(* Logix 5000 project; controller Test vendor 1 type 14 code 92 rev 33.11; software revision 33.00 *)

TASK MainTask (continuous, watchdog 500 ms) : MainProgram

MODULES
   Local : vendor 1 type 14 code 92 (ICP 0, rev 33.11)
      IN : vendor 1 type 7 code 1 (ICP 3, rev 3.2, Input RPI 20 ms)
      O : vendor 1 type 7 code 15 (ICP 2, rev 3.2, Output RPI 20 ms)
      Ethernet : 1756-ENBT (ICP 1, Ethernet 192.168.0.98, rev 6.4)
         IOLM1 : DXM (Ethernet 192.168.0.1, rev 2.22, StandardDataDriven RPI 20 ms)
END_MODULES

TYPE Banner_CL50Pro_PDO_v4 :   // UDT that records the converted prcoess data.
STRUCT
   Color1 : SINT;   // 0 = Green, 1 = Red, 2 = Orange, 3 = Amber, 4 = Yellow, 5 = Lime Green, 6 = Spring Green, 7 = Cyan, 8 = SKy Blue, 9 = Blue, 10 = Violet, 11 = Magenta, 12 = Rose, 13 = White, 14 Custom 1, 15 = Custom 2.
   Color2 : SINT;   // 0 = Green, 1 = Red, 2 = Orange, 3 = Amber, 4 = Yellow, 5 = Lime Green, 6 = Spring Green, 7 = Cyan, 8 = SKy Blue, 9 = Blue, 10 = Violet, 11 = Magenta, 12 = Rose, 13 = White, 14 Custom 1, 15 = Custom 2.
   Animation : SINT;   // 0 = Off, 1 = Steady, 2 = Flash, 3 = Two Color Flash, 5 = Intensity Sweep
   Pulse_Pattern : SINT;   // 0 = Normal, 1 = Strobe, 2 = Three Pulse, 3 = SOS, 4 = Random
   Speed : SINT;   // 0 = Medium, 1 = Fast, 2 = Slow
   Color1_Intensity : SINT;   // 0 = High, 1 = Low, 2 = Medium, 3 = Off, 4 = Custom
   Color2_Intensity : SINT;   // 0 = High, 1 = Low, 2 = Medium, 3 = Off, 4 = Custom
   Audible_State : SINT;   // 0 = Off, 1 = On, 2 = Pulsed, 3 = SOS Pulse
   PDO_DT : SINT[4];
END_STRUCT
END_TYPE

TYPE Banner_CL50Pro_RD_v4 :   // UDT with all of the Read only parameters for CL50 Pro.
STRUCT
   Master_Cycle_Time : INT;
   Min_Cycle_Time : INT;
   M_Sequence_Capability : INT;
   IO_Link_Version_ID : INT;
   Process_Data_Input_Length : INT;
   Process_Data_Output_Length : INT;
   Combined_Vendor_ID : DINT;   // IO-Link Vendor ID
   Vendor_ID1 : INT;
   Vendor_ID2 : INT;
   Combined_Device_ID : DINT;   // IO-Link Device ID
   Device_ID1 : INT;
   Device_ID2 : INT;
   Device_ID3 : INT;
   Serial_Number : STRING;
END_STRUCT
END_TYPE

TYPE Banner_CL50Pro_v4 :   // UDT with all of the parameters for CL50 Pro.
STRUCT
   Initial_Global_Read : BOOL;   // Determines if all of the IO-Link data has been read into the PLC yet
   Command : INT;   // Value placed in here will activate a read or write to a specifc IO-Link Index
   Read_Data : Banner_CL50Pro_RD_v4;   // All read data
   Write_Data : Banner_CL50Pro_WD_v4;   // All data that can be written to.
   Archive : Banner_CL50Pro_WD_v4;   // Archive of the write data.
   Reset : BOOL;
END_STRUCT
END_TYPE

TYPE Banner_CL50Pro_WD_v4 :   // UDT that stores the Write Data for a CL50 Pro.
STRUCT
   System_Command : INT;   // See IODD file for list of commands that can be activated via the System Command interface
   Parameter_Access_Lock : SINT;   // Write access to all read/write parameters is block when this bit is ON.
   Data_Storage_Lock : SINT;   // Data storage mechanism is inhibited when bit is ON.
   Local_Parameterization_Lock : SINT;   // Parameteriation via local control elementes is inhibited.
   Local_User_Interface_Lock : SINT;   // Operation of the hmi on the device is disabled.
   Operating_Mode : SINT;   // 2 = Run Mode
   Custom_Intensity : SINT;   // 0 to 100 %
   Custom_Flash_Rate : INT;   // Range 5 to 255 (.5 to 25.5 converted rate).
   Number_of_Segments : INT;   // Number of Segments for Scroll and Bounce in the primary color.
   Restrict_to_Gamut : SINT;   // 0 = Off, 1 = On. Turn on to show more consistent colors from segment to segment.
   Disable_Parameter_Data : SINT;   // 0 = Disable, 1 = Enabled.
   Reserved : SINT;
   CC1_Red : INT;   // 0-255. Custom 1 Red.
   CC1_Green : INT;   // 0-255. Custom 1 Green.
   CC1_Blue : INT;   // 0-255. Custom 1 Blue.
   CC2_Red : INT;   // 0-255. Custom 2 Red.
   CC2_Green : INT;   // 0-255. Custom 2 Green.
   CC2_Blue : INT;   // 0-255. Custom 2 Blue.
END_STRUCT
END_TYPE

TYPE Banner_IOL_Port_v4 :   // UDT that has all of the data items necessary to communicate with a specific Port on a IO-Link Master
STRUCT
   Port_Controlled : INT;   // Each bit represents a port on an IO-Link Master. Set to 1 to tell AOI to control that port.
   Port_Activate : INT;   // Each bit represents a port on an IO-Link Master. When ON that port will process any commands in queue.
   Port_Read : INT;   // Each bit represents a port on an IO-Link Master. Used to determine when device AOI has requested a Read command.
   Port_Write : INT;   // Each bit represents a port on an IO-Link Master. Used to determine when device AOI has requested a Write command.
   Port_RW_Complete : INT;   // Each bit represents a port on an IO-Link Master. Tells device AOI that Read or Write request has been completed.
   Port_Device_Read : INT;
   Data_Transfer : SINT[190];   // Array to transfer data from IO-Master to device AOIs.
END_STRUCT
END_TYPE

TYPE Banner_IOLM_EL_v4 :   // Error Log for Messages to IOLM.
STRUCT
   RW : SINT;   // 0 = Read, 1 = Write.
   Port : SINT;   // Port number that generated error.
   Index : INT;   // IO-Link Index for generated error.
END_STRUCT
END_TYPE

TYPE Banner_IOLM_v4 :   // UDT to control IO-Link Masters.
STRUCT
   Message_Source_Data : SINT[190];
   Message_Destination_Data : SINT[190];
   Error_Log : Banner_IOLM_EL_v4[10];
   Error_Write_Retry : BOOL;
   Num_Error_MSGS : DINT;
   IO_Link_Master_Busy : BOOL;   // 0 = While waiting for a command, 1 = Processing command
   AOI_Reset : BOOL;
   Port_Data : Banner_IOL_Port_v4;   // All of the necessary data to work with the various ports of the IO-Link Master.
   Halt_Operation : BOOL;   // When parameter is 1 the AOI is halted as next available time frame.
   AOI_Halted : BOOL;   // AOI is in standby mode until Halt Operation tag is set back to 0.
END_STRUCT
END_TYPE

ADD_ON_INSTRUCTION Banner_CL50Pro_Param_v4   (* revision 4.0, vendor Banner Engineering *)
// AOI to read and write parameter data to an IO-Link CL50 Pro.
VAR_IN_OUT
   CL50Pro : Banner_CL50Pro_v4; {required}
   Port_Data : Banner_IOL_Port_v4; {required}
END_VAR
VAR_INPUT
   Port : DINT; {required}
END_VAR
VAR
   Local_Control : DINT; {access None}
   Global_Read_Command_Value : INT; {access None}
   Global_Write_Command_Value : INT; {access None}
   Command_Being_Processed : BOOL; {access None}
   Update_Archive : BOOL; {access None}
   Index_Write_Control : DINT; {access None}
   Index_Write_Inprocess : INT; {access None}
   Temp_Excess_Gain : DINT[2]; {access None}
   Inprocess_Index : DINT; {access None}
   SP_Index : DINT; {access None}   // State Parameters Index
   SP_Write_Index : DINT; {access None}
   SP_R_Index : DINT; {access None}
   SP_W_Index : DINT; {access None}
END_VAR

ROUTINE Logic   (* ladder *)
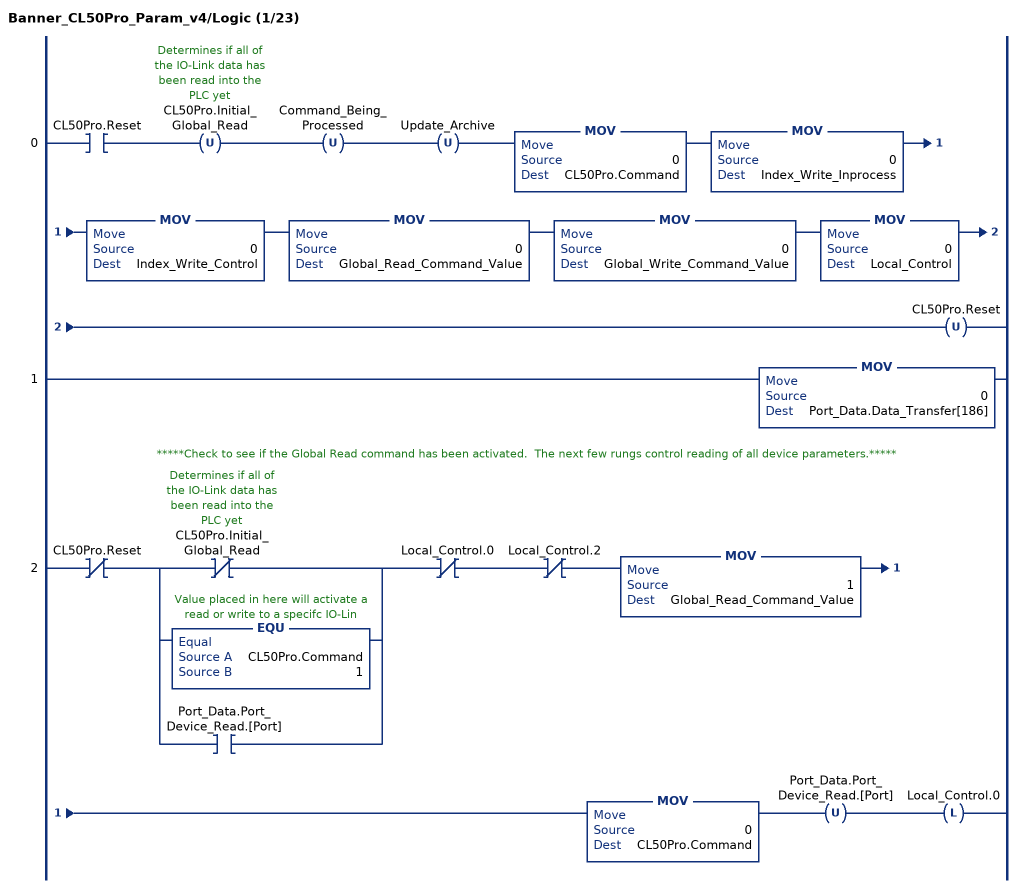
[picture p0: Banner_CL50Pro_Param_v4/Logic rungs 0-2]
   0: XIC(CL50Pro.Reset)OTU(CL50Pro.Initial_Global_Read)OTU(Command_Being_Processed)OTU(Update_Archive)MOV(0,CL50Pro.Command)MOV(0,Index_Write_Inprocess)MOV(0,Index_Write_Control)MOV(0,Global_Read_Command_Value)MOV(0,Global_Write_Command_Value)MOV(0,Local_Control)OTU(CL50Pro.Reset);
   1: MOV(0,Port_Data.Data_Transfer[186]);
   // *****Check to see if the Global Read command has been activated.  The next few rungs control reading of all device parameters.*****
   2: XIO(CL50Pro.Reset)[XIO(CL50Pro.Initial_Global_Read) ,EQU(CL50Pro.Command,1) ,XIC(Port_Data.Port_Device_Read.[Port]) ]XIO(Local_Control.0)XIO(Local_Control.2)MOV(1,Global_Read_Command_Value)MOV(0,CL50Pro.Command)OTU(Port_Data.Port_Device_Read.[Port])OTL(Local_Control.0);
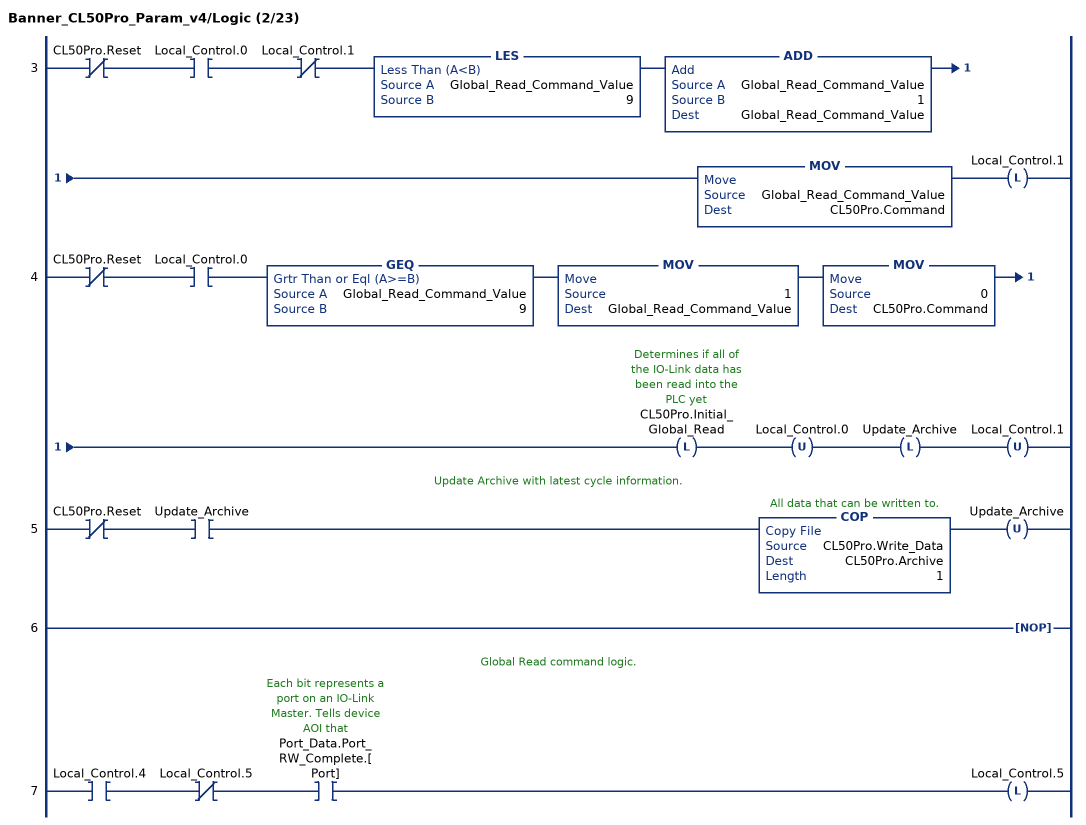
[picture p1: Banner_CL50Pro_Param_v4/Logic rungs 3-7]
   3: XIO(CL50Pro.Reset)XIC(Local_Control.0)XIO(Local_Control.1)LES(Global_Read_Command_Value,9)ADD(Global_Read_Command_Value,1,Global_Read_Command_Value)MOV(Global_Read_Command_Value,CL50Pro.Command)OTL(Local_Control.1);
   4: XIO(CL50Pro.Reset)XIC(Local_Control.0)GEQ(Global_Read_Command_Value,9)MOV(1,Global_Read_Command_Value)MOV(0,CL50Pro.Command)OTL(CL50Pro.Initial_Global_Read)OTU(Local_Control.0)OTL(Update_Archive)OTU(Local_Control.1);
   // Update Archive with latest cycle information.
   5: XIO(CL50Pro.Reset)XIC(Update_Archive)COP(CL50Pro.Write_Data,CL50Pro.Archive,1)OTU(Update_Archive);
   6: NOP();
   // Global Read command logic.
   7: XIC(Local_Control.4)XIO(Local_Control.5)XIC(Port_Data.Port_RW_Complete.[Port])OTL(Local_Control.5);
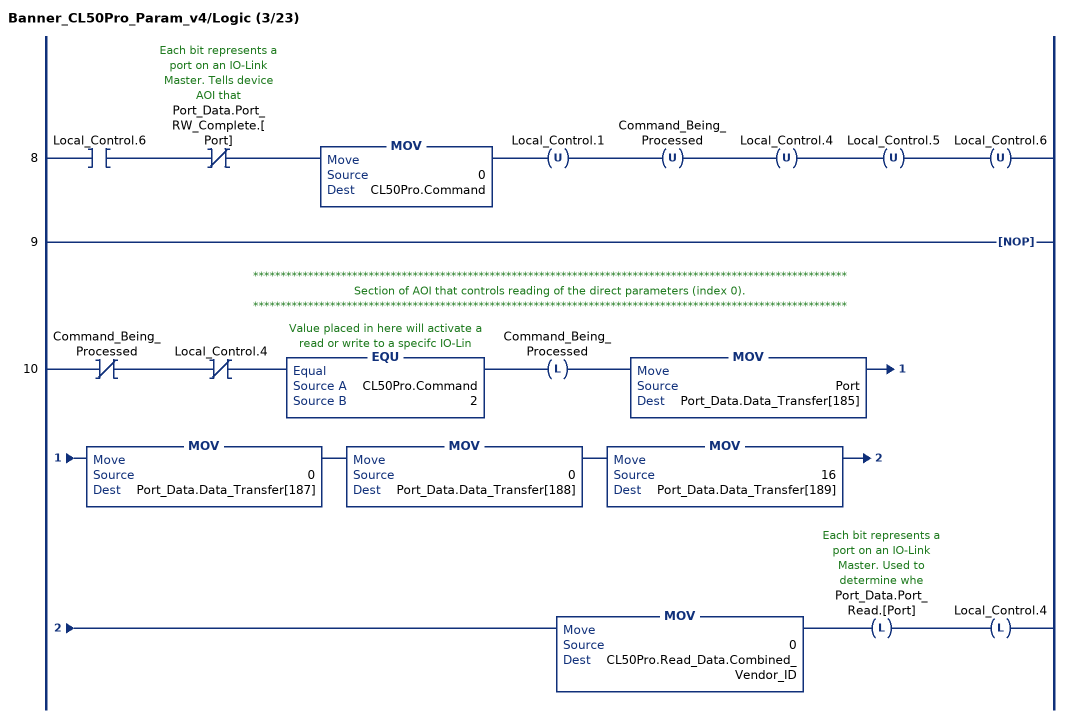
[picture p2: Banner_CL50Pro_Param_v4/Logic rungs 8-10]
   8: XIC(Local_Control.6)XIO(Port_Data.Port_RW_Complete.[Port])MOV(0,CL50Pro.Command)OTU(Local_Control.1)OTU(Command_Being_Processed)OTU(Local_Control.4)OTU(Local_Control.5)OTU(Local_Control.6);
   9: NOP();
   // ************************************************************************************************************
   // Section of AOI that controls reading of the direct parameters (index 0).
   // ************************************************************************************************************
   10: XIO(Command_Being_Processed)XIO(Local_Control.4)EQU(CL50Pro.Command,2)OTL(Command_Being_Processed)MOV(Port,Port_Data.Data_Transfer[185])MOV(0,Port_Data.Data_Transfer[187])MOV(0,Port_Data.Data_Transfer[188])MOV(16,Port_Data.Data_Transfer[189])MOV(0,CL50Pro.Read_Data.Combined_Vendor_ID)OTL(Port_Data.Port_Read.[Port])OTL(Local_Control.4);
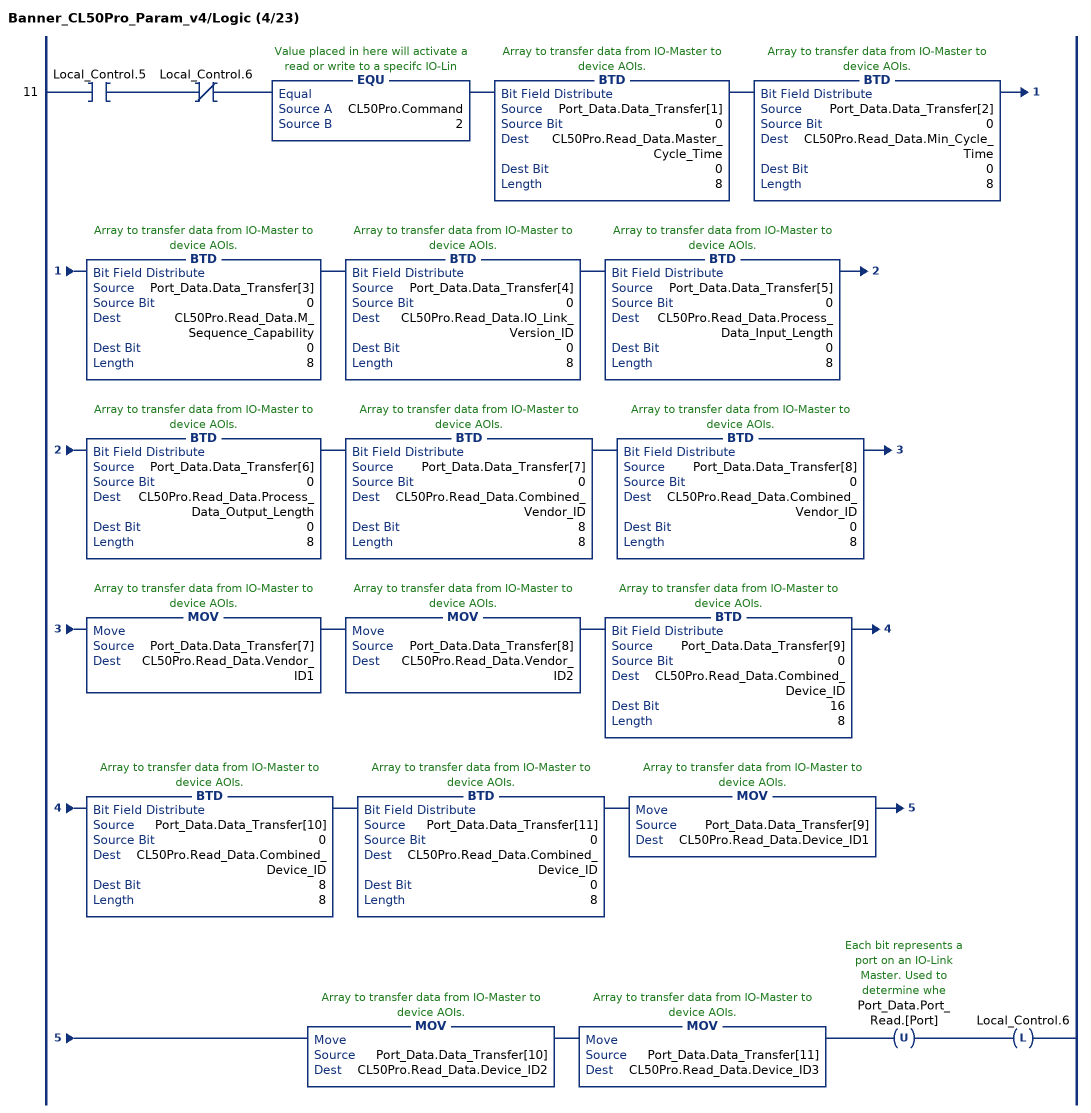
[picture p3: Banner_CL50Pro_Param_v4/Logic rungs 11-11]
   11: XIC(Local_Control.5)XIO(Local_Control.6)EQU(CL50Pro.Command,2)BTD(Port_Data.Data_Transfer[1],0,CL50Pro.Read_Data.Master_Cycle_Time,0,8)BTD(Port_Data.Data_Transfer[2],0,CL50Pro.Read_Data.Min_Cycle_Time,0,8)BTD(Port_Data.Data_Transfer[3],0,CL50Pro.Read_Data.M_Sequence_Capability,0,8)BTD(Port_Data.Data_Transfer[4],0,CL50Pro.Read_Data.IO_Link_Version_ID,0,8)BTD(Port_Data.Data_Transfer[5],0,CL50Pro.Read_Data.Process_Data_Input_Length,0,8)BTD(Port_Data.Data_Transfer[6],0,CL50Pro.Read_Data.Process_Data_Output_Length,0,8)BTD(Port_Data.Data_Transfer[7],0,CL50Pro.Read_Data.Combined_Vendor_ID,8,8)BTD(Port_Data.Data_Transfer[8],0,CL50Pro.Read_Data.Combined_Vendor_ID,0,8)MOV(Port_Data.Data_Transfer[7],CL50Pro.Read_Data.Vendor_ID1)MOV(Port_Data.Data_Transfer[8],CL50Pro.Read_Data.Vendor_ID2)BTD(Port_Data.Data_Transfer[9],0,CL50Pro.Read_Data.Combined_Device_ID,16,8)BTD(Port_Data.Data_Transfer[10],0,CL50Pro.Read_Data.Combined_Device_ID,8,8)BTD(Port_Data.Data_Transfer[11],0,CL50Pro.Read_Data.Combined_Device_ID,0,8)MOV(Port_Data.Data_Transfer[9],CL50Pro.Read_Data.Device_ID1)MOV(Port_Data.Data_Transfer[10],CL50Pro.Read_Data.Device_ID2)MOV(Port_Data.Data_Transfer[11],CL50Pro.Read_Data.Device_ID3)OTU(Port_Data.Port_Read.[Port])OTL(Local_Control.6);
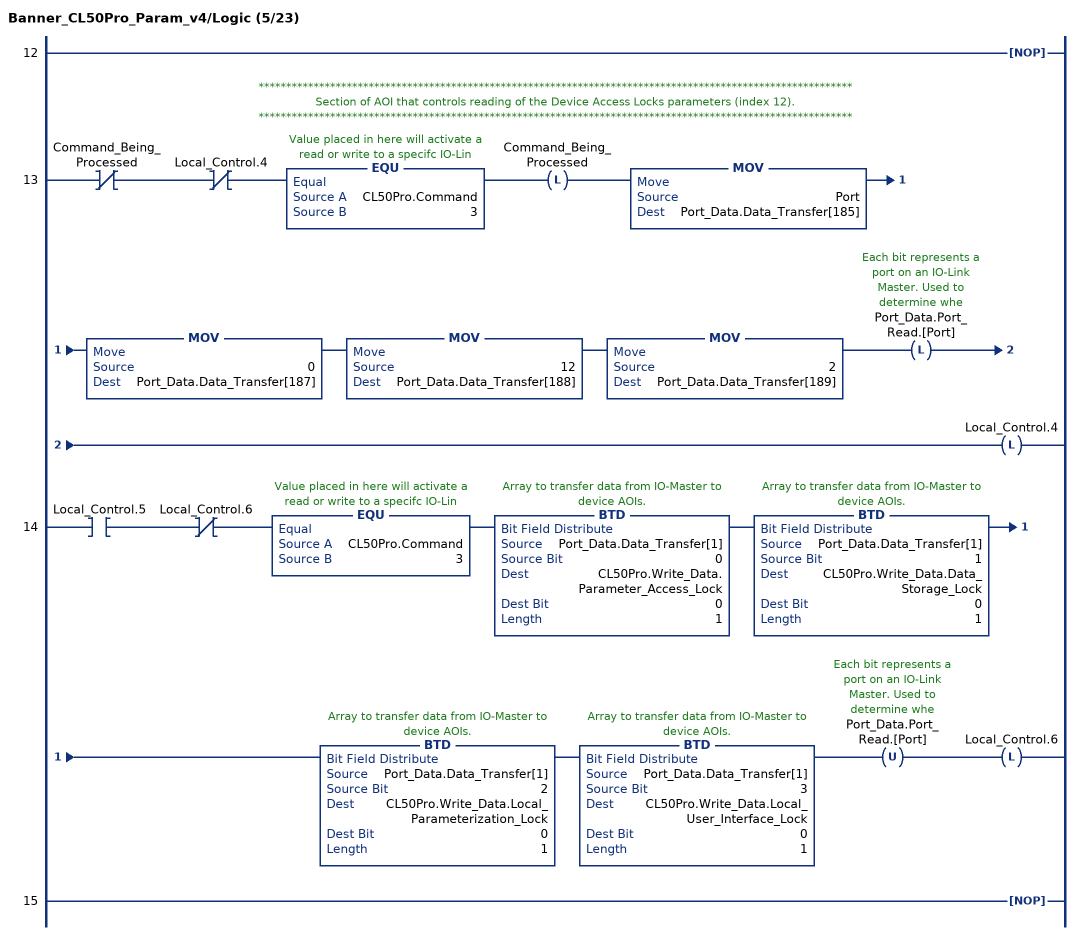
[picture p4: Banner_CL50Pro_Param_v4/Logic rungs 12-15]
   12: NOP();
   // ************************************************************************************************************
   // Section of AOI that controls reading of the Device Access Locks parameters (index 12).
   // ************************************************************************************************************
   13: XIO(Command_Being_Processed)XIO(Local_Control.4)EQU(CL50Pro.Command,3)OTL(Command_Being_Processed)MOV(Port,Port_Data.Data_Transfer[185])MOV(0,Port_Data.Data_Transfer[187])MOV(12,Port_Data.Data_Transfer[188])MOV(2,Port_Data.Data_Transfer[189])OTL(Port_Data.Port_Read.[Port])OTL(Local_Control.4);
   14: XIC(Local_Control.5)XIO(Local_Control.6)EQU(CL50Pro.Command,3)BTD(Port_Data.Data_Transfer[1],0,CL50Pro.Write_Data.Parameter_Access_Lock,0,1)BTD(Port_Data.Data_Transfer[1],1,CL50Pro.Write_Data.Data_Storage_Lock,0,1)BTD(Port_Data.Data_Transfer[1],2,CL50Pro.Write_Data.Local_Parameterization_Lock,0,1)BTD(Port_Data.Data_Transfer[1],3,CL50Pro.Write_Data.Local_User_Interface_Lock,0,1)OTU(Port_Data.Port_Read.[Port])OTL(Local_Control.6);
   15: NOP();
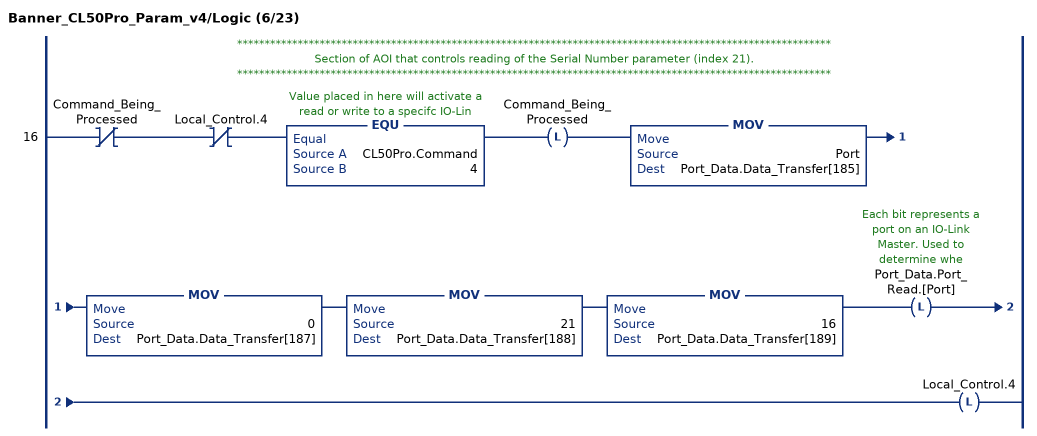
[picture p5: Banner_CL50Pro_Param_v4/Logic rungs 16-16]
   // ************************************************************************************************************
   // Section of AOI that controls reading of the Serial Number parameter (index 21).
   // ************************************************************************************************************
   16: XIO(Command_Being_Processed)XIO(Local_Control.4)EQU(CL50Pro.Command,4)OTL(Command_Being_Processed)MOV(Port,Port_Data.Data_Transfer[185])MOV(0,Port_Data.Data_Transfer[187])MOV(21,Port_Data.Data_Transfer[188])MOV(16,Port_Data.Data_Transfer[189])OTL(Port_Data.Port_Read.[Port])OTL(Local_Control.4);
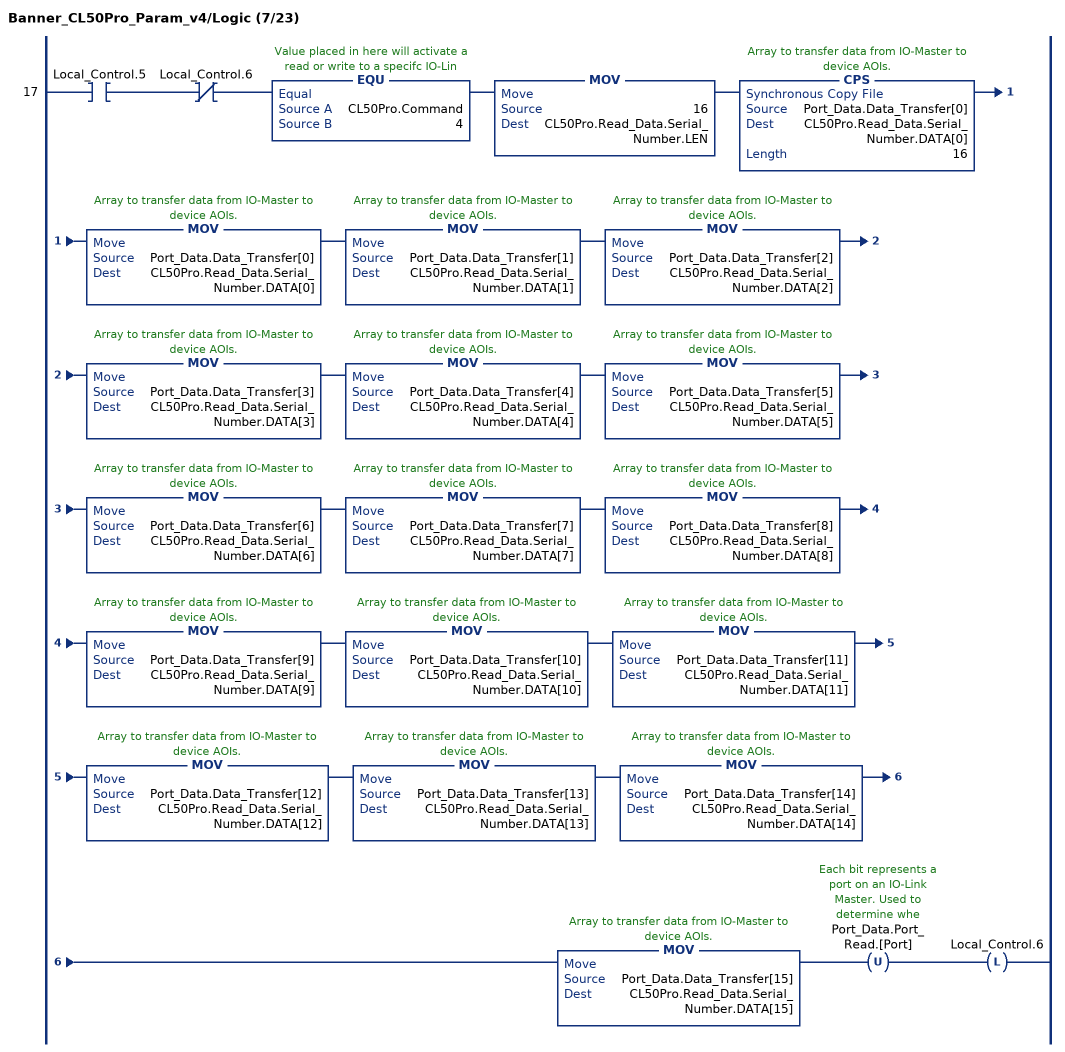
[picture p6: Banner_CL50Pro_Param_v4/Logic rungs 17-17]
   17: XIC(Local_Control.5)XIO(Local_Control.6)EQU(CL50Pro.Command,4)MOV(16,CL50Pro.Read_Data.Serial_Number.LEN)CPS(Port_Data.Data_Transfer[0],CL50Pro.Read_Data.Serial_Number.DATA[0],16)MOV(Port_Data.Data_Transfer[0],CL50Pro.Read_Data.Serial_Number.DATA[0])MOV(Port_Data.Data_Transfer[1],CL50Pro.Read_Data.Serial_Number.DATA[1])MOV(Port_Data.Data_Transfer[2],CL50Pro.Read_Data.Serial_Number.DATA[2])MOV(Port_Data.Data_Transfer[3],CL50Pro.Read_Data.Serial_Number.DATA[3])MOV(Port_Data.Data_Transfer[4],CL50Pro.Read_Data.Serial_Number.DATA[4])MOV(Port_Data.Data_Transfer[5],CL50Pro.Read_Data.Serial_Number.DATA[5])MOV(Port_Data.Data_Transfer[6],CL50Pro.Read_Data.Serial_Number.DATA[6])MOV(Port_Data.Data_Transfer[7],CL50Pro.Read_Data.Serial_Number.DATA[7])MOV(Port_Data.Data_Transfer[8],CL50Pro.Read_Data.Serial_Number.DATA[8])MOV(Port_Data.Data_Transfer[9],CL50Pro.Read_Data.Serial_Number.DATA[9])MOV(Port_Data.Data_Transfer[10],CL50Pro.Read_Data.Serial_Number.DATA[10])MOV(Port_Data.Data_Transfer[11],CL50Pro.Read_Data.Serial_Number.DATA[11])MOV(Port_Data.Data_Transfer[12],CL50Pro.Read_Data.Serial_Number.DATA[12])MOV(Port_Data.Data_Transfer[13],CL50Pro.Read_Data.Serial_Number.DATA[13])MOV(Port_Data.Data_Transfer[14],CL50Pro.Read_Data.Serial_Number.DATA[14])MOV(Port_Data.Data_Transfer[15],CL50Pro.Read_Data.Serial_Number.DATA[15])OTU(Port_Data.Port_Read.[Port])OTL(Local_Control.6);
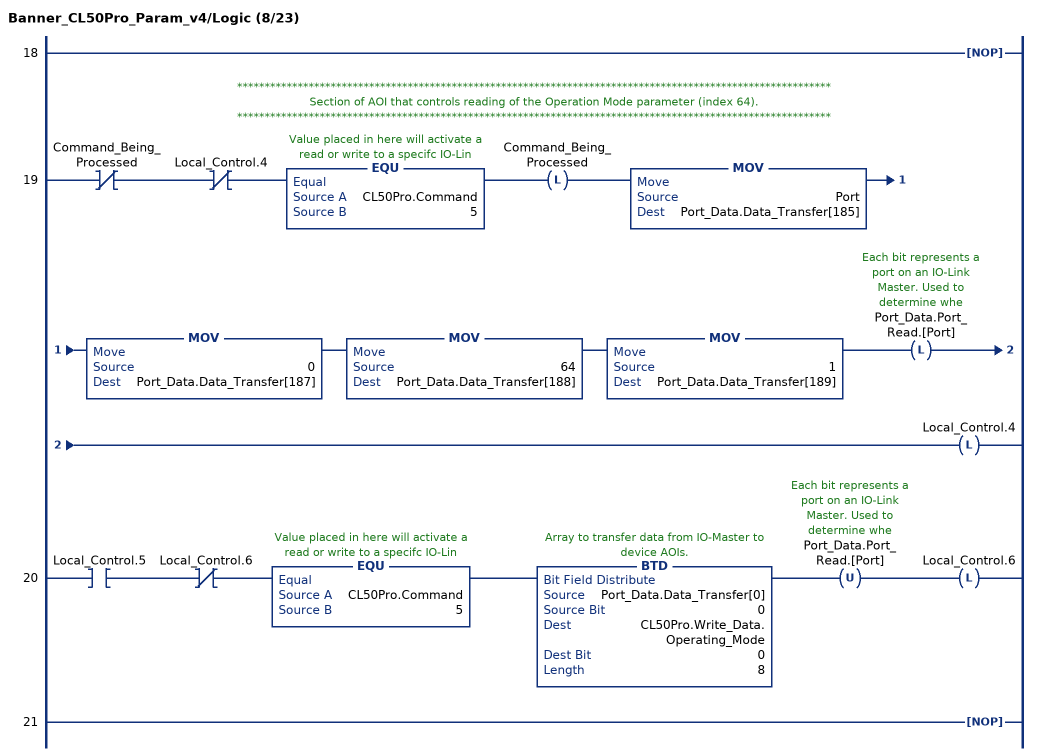
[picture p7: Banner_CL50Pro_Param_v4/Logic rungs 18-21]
   18: NOP();
   // ************************************************************************************************************
   // Section of AOI that controls reading of the Operation Mode parameter (index 64).
   // ************************************************************************************************************
   19: XIO(Command_Being_Processed)XIO(Local_Control.4)EQU(CL50Pro.Command,5)OTL(Command_Being_Processed)MOV(Port,Port_Data.Data_Transfer[185])MOV(0,Port_Data.Data_Transfer[187])MOV(64,Port_Data.Data_Transfer[188])MOV(1,Port_Data.Data_Transfer[189])OTL(Port_Data.Port_Read.[Port])OTL(Local_Control.4);
   20: XIC(Local_Control.5)XIO(Local_Control.6)EQU(CL50Pro.Command,5)BTD(Port_Data.Data_Transfer[0],0,CL50Pro.Write_Data.Operating_Mode,0,8)OTU(Port_Data.Port_Read.[Port])OTL(Local_Control.6);
   21: NOP();
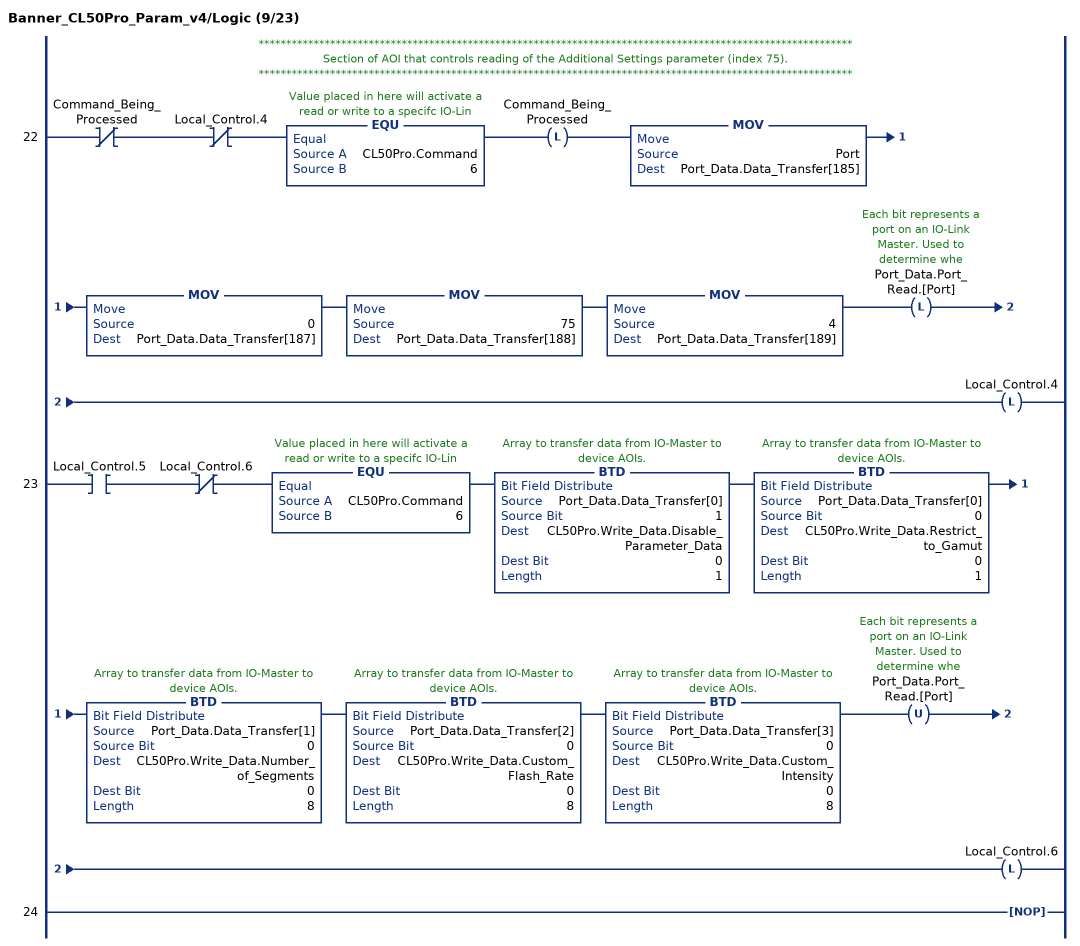
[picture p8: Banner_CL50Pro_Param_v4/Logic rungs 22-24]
   // ************************************************************************************************************
   // Section of AOI that controls reading of the Additional Settings parameter (index 75).
   // ************************************************************************************************************
   22: XIO(Command_Being_Processed)XIO(Local_Control.4)EQU(CL50Pro.Command,6)OTL(Command_Being_Processed)MOV(Port,Port_Data.Data_Transfer[185])MOV(0,Port_Data.Data_Transfer[187])MOV(75,Port_Data.Data_Transfer[188])MOV(4,Port_Data.Data_Transfer[189])OTL(Port_Data.Port_Read.[Port])OTL(Local_Control.4);
   23: XIC(Local_Control.5)XIO(Local_Control.6)EQU(CL50Pro.Command,6)BTD(Port_Data.Data_Transfer[0],1,CL50Pro.Write_Data.Disable_Parameter_Data,0,1)BTD(Port_Data.Data_Transfer[0],0,CL50Pro.Write_Data.Restrict_to_Gamut,0,1)BTD(Port_Data.Data_Transfer[1],0,CL50Pro.Write_Data.Number_of_Segments,0,8)BTD(Port_Data.Data_Transfer[2],0,CL50Pro.Write_Data.Custom_Flash_Rate,0,8)BTD(Port_Data.Data_Transfer[3],0,CL50Pro.Write_Data.Custom_Intensity,0,8)OTU(Port_Data.Port_Read.[Port])OTL(Local_Control.6);
   24: NOP();
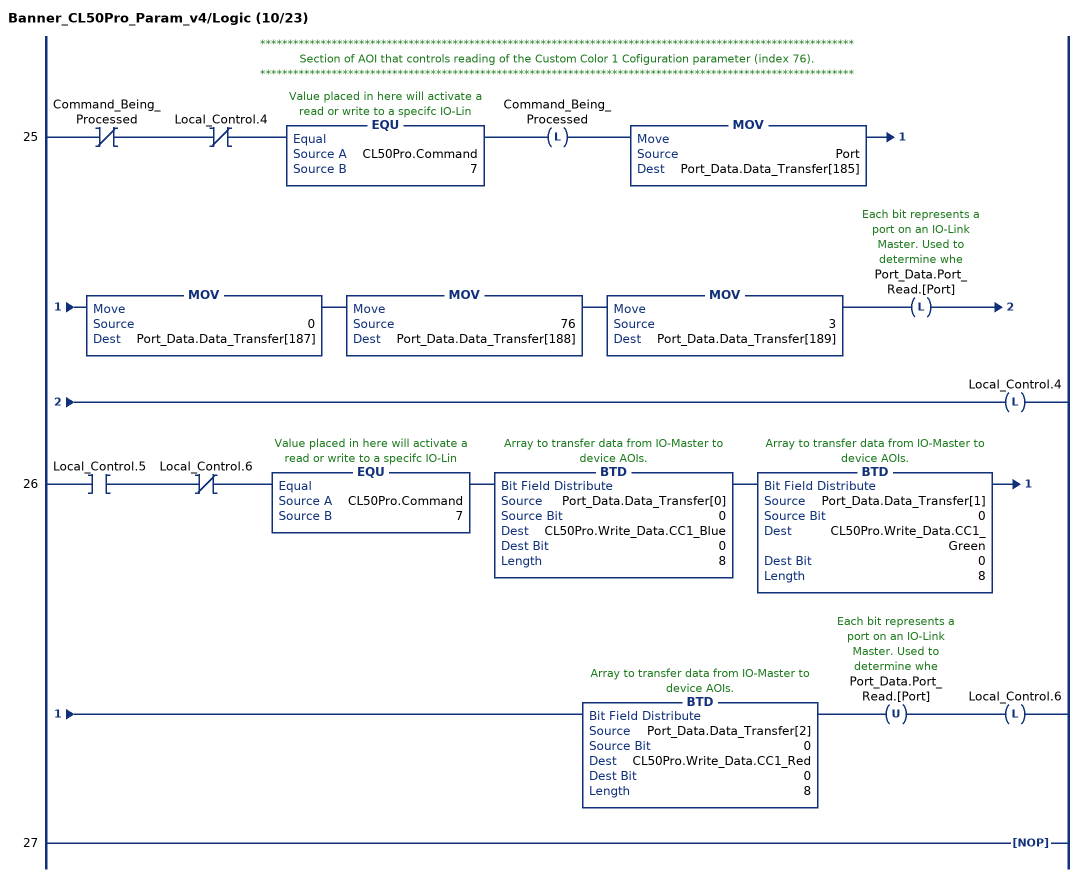
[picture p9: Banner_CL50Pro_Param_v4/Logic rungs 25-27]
   // ************************************************************************************************************
   // Section of AOI that controls reading of the Custom Color 1 Cofiguration parameter (index 76).
   // ************************************************************************************************************
   25: XIO(Command_Being_Processed)XIO(Local_Control.4)EQU(CL50Pro.Command,7)OTL(Command_Being_Processed)MOV(Port,Port_Data.Data_Transfer[185])MOV(0,Port_Data.Data_Transfer[187])MOV(76,Port_Data.Data_Transfer[188])MOV(3,Port_Data.Data_Transfer[189])OTL(Port_Data.Port_Read.[Port])OTL(Local_Control.4);
   26: XIC(Local_Control.5)XIO(Local_Control.6)EQU(CL50Pro.Command,7)BTD(Port_Data.Data_Transfer[0],0,CL50Pro.Write_Data.CC1_Blue,0,8)BTD(Port_Data.Data_Transfer[1],0,CL50Pro.Write_Data.CC1_Green,0,8)BTD(Port_Data.Data_Transfer[2],0,CL50Pro.Write_Data.CC1_Red,0,8)OTU(Port_Data.Port_Read.[Port])OTL(Local_Control.6);
   27: NOP();
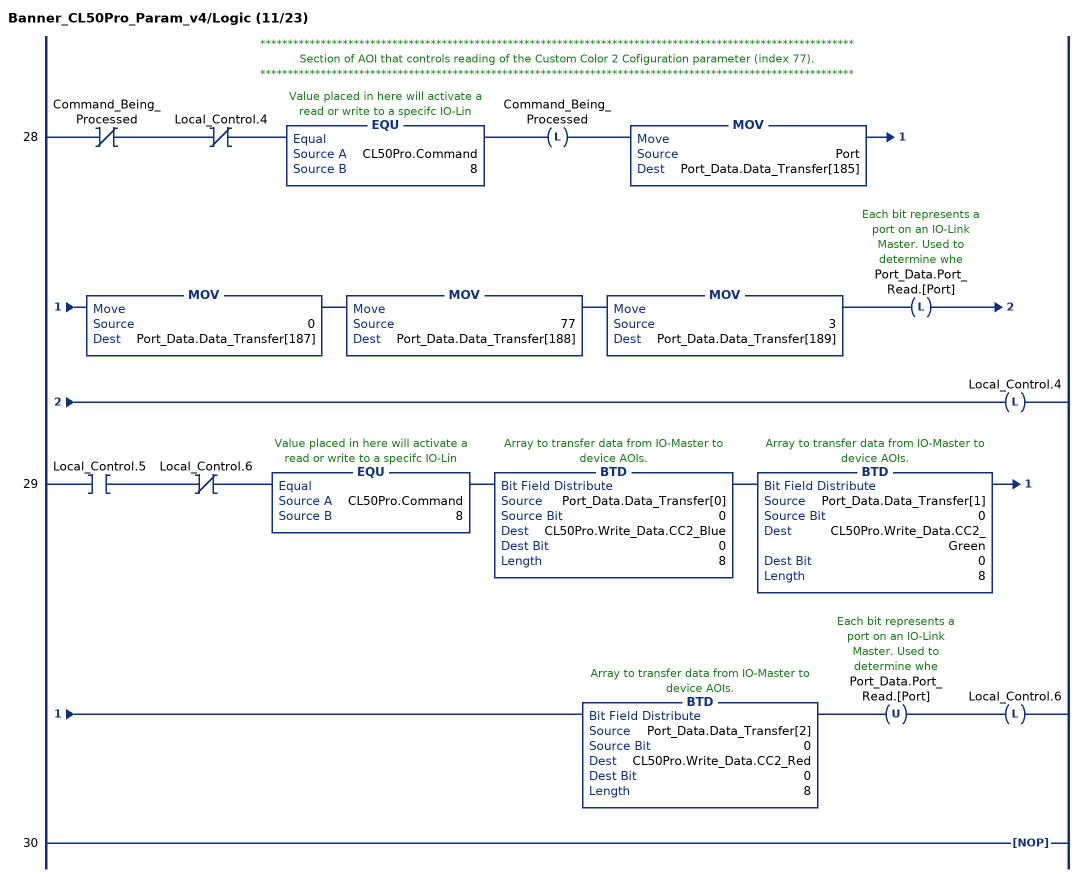
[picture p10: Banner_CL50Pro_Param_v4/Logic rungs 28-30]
   // ************************************************************************************************************
   // Section of AOI that controls reading of the Custom Color 2 Cofiguration parameter (index 77).
   // ************************************************************************************************************
   28: XIO(Command_Being_Processed)XIO(Local_Control.4)EQU(CL50Pro.Command,8)OTL(Command_Being_Processed)MOV(Port,Port_Data.Data_Transfer[185])MOV(0,Port_Data.Data_Transfer[187])MOV(77,Port_Data.Data_Transfer[188])MOV(3,Port_Data.Data_Transfer[189])OTL(Port_Data.Port_Read.[Port])OTL(Local_Control.4);
   29: XIC(Local_Control.5)XIO(Local_Control.6)EQU(CL50Pro.Command,8)BTD(Port_Data.Data_Transfer[0],0,CL50Pro.Write_Data.CC2_Blue,0,8)BTD(Port_Data.Data_Transfer[1],0,CL50Pro.Write_Data.CC2_Green,0,8)BTD(Port_Data.Data_Transfer[2],0,CL50Pro.Write_Data.CC2_Red,0,8)OTU(Port_Data.Port_Read.[Port])OTL(Local_Control.6);
   30: NOP();
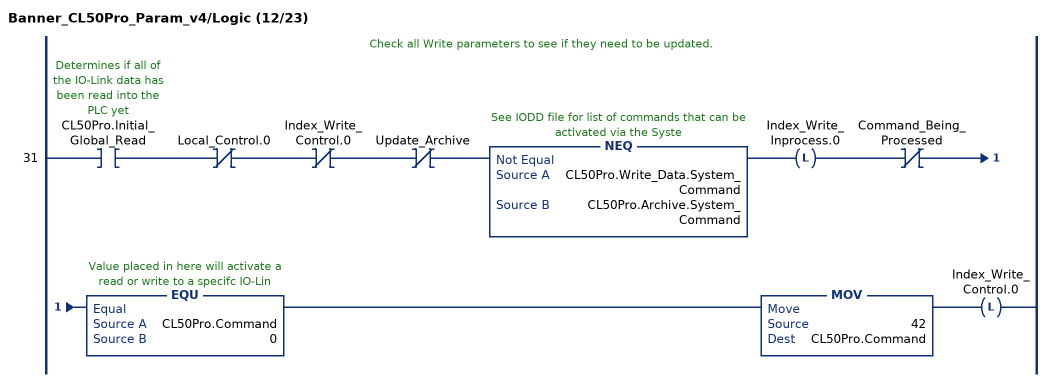
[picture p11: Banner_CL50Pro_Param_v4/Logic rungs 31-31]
   // Check all Write parameters to see if they need to be updated.
   31: XIC(CL50Pro.Initial_Global_Read)XIO(Local_Control.0)XIO(Index_Write_Control.0)XIO(Update_Archive)NEQ(CL50Pro.Write_Data.System_Command,CL50Pro.Archive.System_Command)OTL(Index_Write_Inprocess.0)XIO(Command_Being_Processed)EQU(CL50Pro.Command,0)MOV(42,CL50Pro.Command)OTL(Index_Write_Control.0);
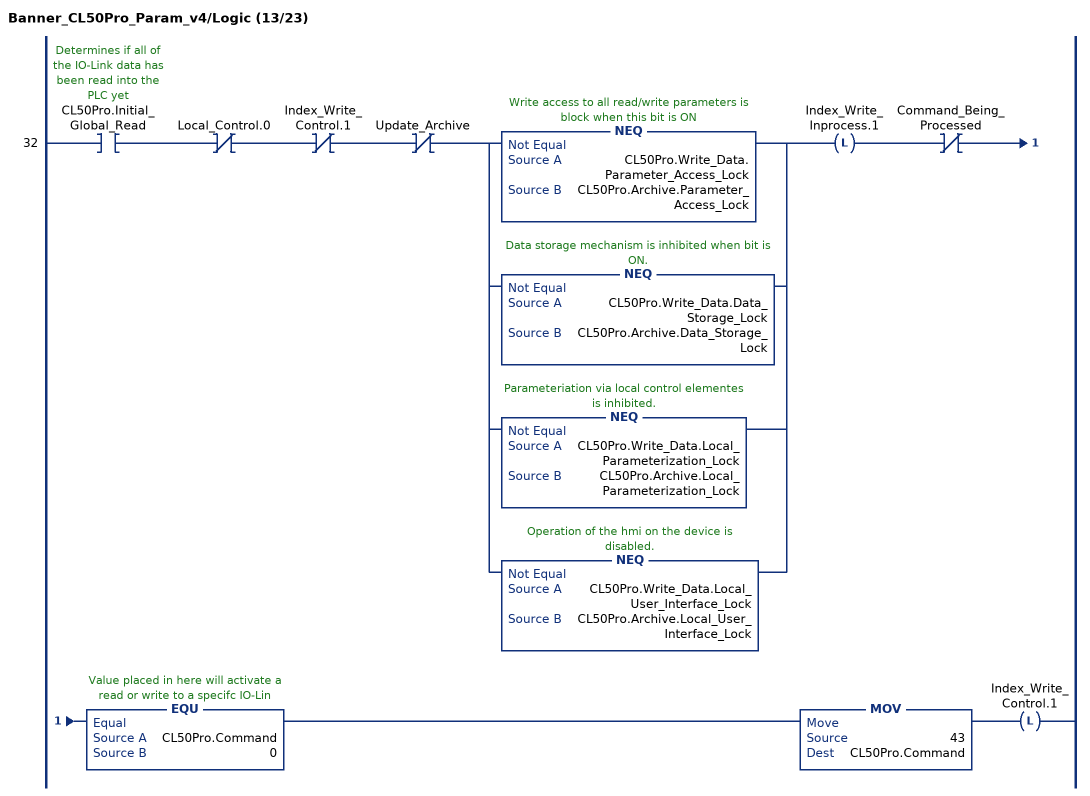
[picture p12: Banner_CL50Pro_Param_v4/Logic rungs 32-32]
   32: XIC(CL50Pro.Initial_Global_Read)XIO(Local_Control.0)XIO(Index_Write_Control.1)XIO(Update_Archive)[NEQ(CL50Pro.Write_Data.Parameter_Access_Lock,CL50Pro.Archive.Parameter_Access_Lock) ,NEQ(CL50Pro.Write_Data.Data_Storage_Lock,CL50Pro.Archive.Data_Storage_Lock) ,NEQ(CL50Pro.Write_Data.Local_Parameterization_Lock,CL50Pro.Archive.Local_Parameterization_Lock) ,NEQ(CL50Pro.Write_Data.Local_User_Interface_Lock,CL50Pro.Archive.Local_User_Interface_Lock) ]OTL(Index_Write_Inprocess.1)XIO(Command_Being_Processed)EQU(CL50Pro.Command,0)MOV(43,CL50Pro.Command)OTL(Index_Write_Control.1);
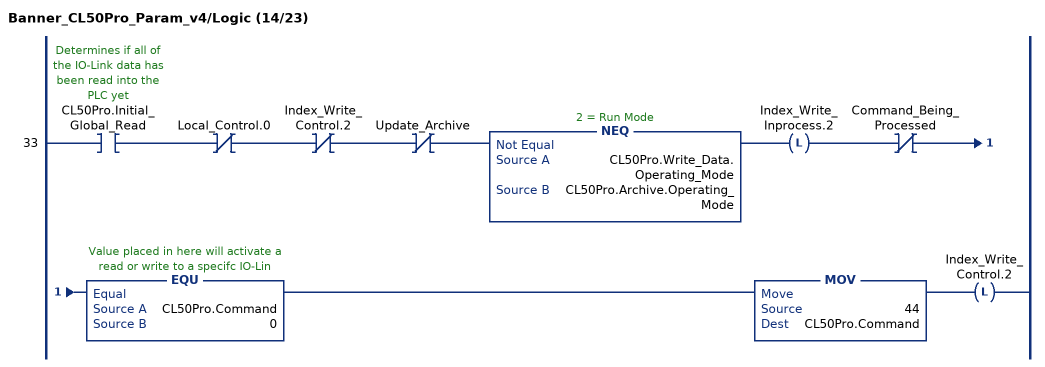
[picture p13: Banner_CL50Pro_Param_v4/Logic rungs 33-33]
   33: XIC(CL50Pro.Initial_Global_Read)XIO(Local_Control.0)XIO(Index_Write_Control.2)XIO(Update_Archive)NEQ(CL50Pro.Write_Data.Operating_Mode,CL50Pro.Archive.Operating_Mode)OTL(Index_Write_Inprocess.2)XIO(Command_Being_Processed)EQU(CL50Pro.Command,0)MOV(44,CL50Pro.Command)OTL(Index_Write_Control.2);
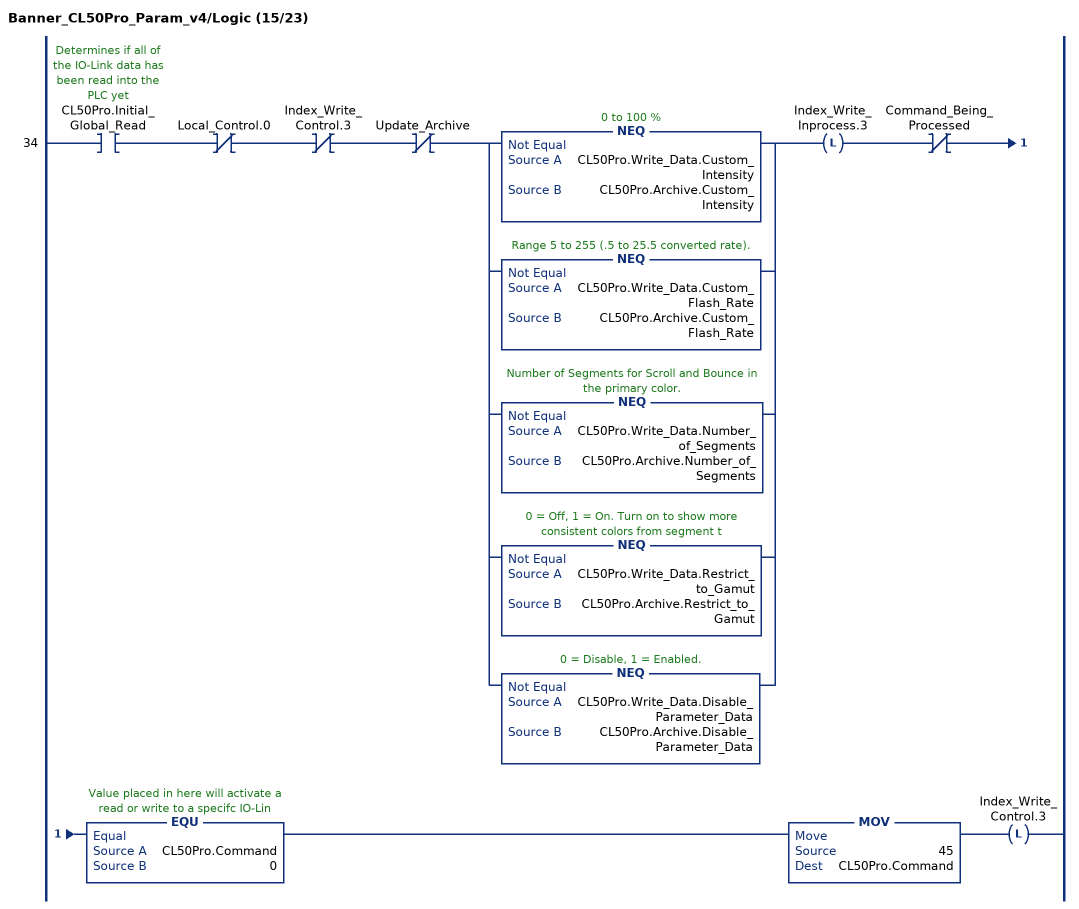
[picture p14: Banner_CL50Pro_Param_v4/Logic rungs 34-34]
   34: XIC(CL50Pro.Initial_Global_Read)XIO(Local_Control.0)XIO(Index_Write_Control.3)XIO(Update_Archive)[NEQ(CL50Pro.Write_Data.Custom_Intensity,CL50Pro.Archive.Custom_Intensity) ,NEQ(CL50Pro.Write_Data.Custom_Flash_Rate,CL50Pro.Archive.Custom_Flash_Rate) ,NEQ(CL50Pro.Write_Data.Number_of_Segments,CL50Pro.Archive.Number_of_Segments) ,NEQ(CL50Pro.Write_Data.Restrict_to_Gamut,CL50Pro.Archive.Restrict_to_Gamut) ,NEQ(CL50Pro.Write_Data.Disable_Parameter_Data,CL50Pro.Archive.Disable_Parameter_Data) ]OTL(Index_Write_Inprocess.3)XIO(Command_Being_Processed)EQU(CL50Pro.Command,0)MOV(45,CL50Pro.Command)OTL(Index_Write_Control.3);
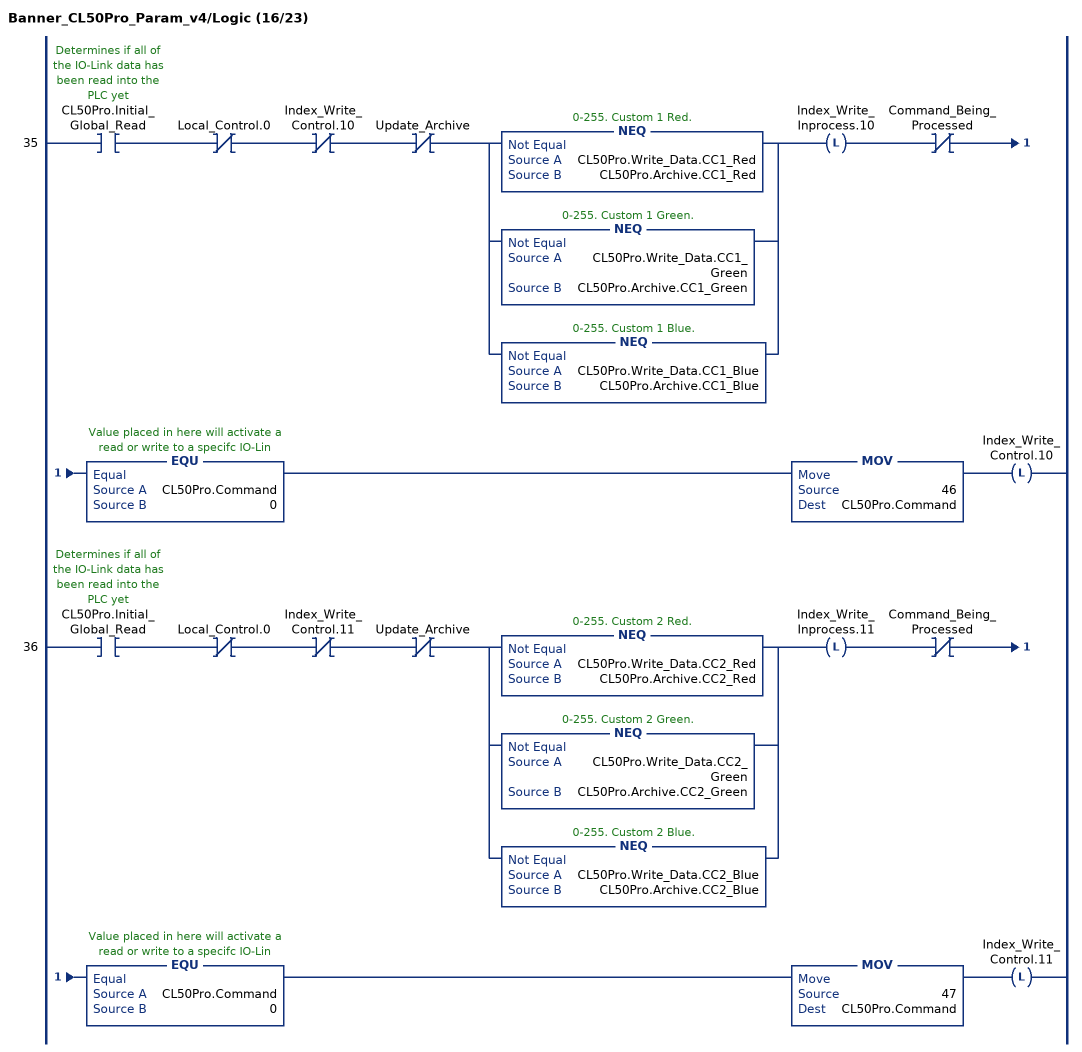
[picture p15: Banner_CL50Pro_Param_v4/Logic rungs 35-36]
   35: XIC(CL50Pro.Initial_Global_Read)XIO(Local_Control.0)XIO(Index_Write_Control.10)XIO(Update_Archive)[NEQ(CL50Pro.Write_Data.CC1_Red,CL50Pro.Archive.CC1_Red) ,NEQ(CL50Pro.Write_Data.CC1_Green,CL50Pro.Archive.CC1_Green) ,NEQ(CL50Pro.Write_Data.CC1_Blue,CL50Pro.Archive.CC1_Blue) ]OTL(Index_Write_Inprocess.10)XIO(Command_Being_Processed)EQU(CL50Pro.Command,0)MOV(46,CL50Pro.Command)OTL(Index_Write_Control.10);
   36: XIC(CL50Pro.Initial_Global_Read)XIO(Local_Control.0)XIO(Index_Write_Control.11)XIO(Update_Archive)[NEQ(CL50Pro.Write_Data.CC2_Red,CL50Pro.Archive.CC2_Red) ,NEQ(CL50Pro.Write_Data.CC2_Green,CL50Pro.Archive.CC2_Green) ,NEQ(CL50Pro.Write_Data.CC2_Blue,CL50Pro.Archive.CC2_Blue) ]OTL(Index_Write_Inprocess.11)XIO(Command_Being_Processed)EQU(CL50Pro.Command,0)MOV(47,CL50Pro.Command)OTL(Index_Write_Control.11);
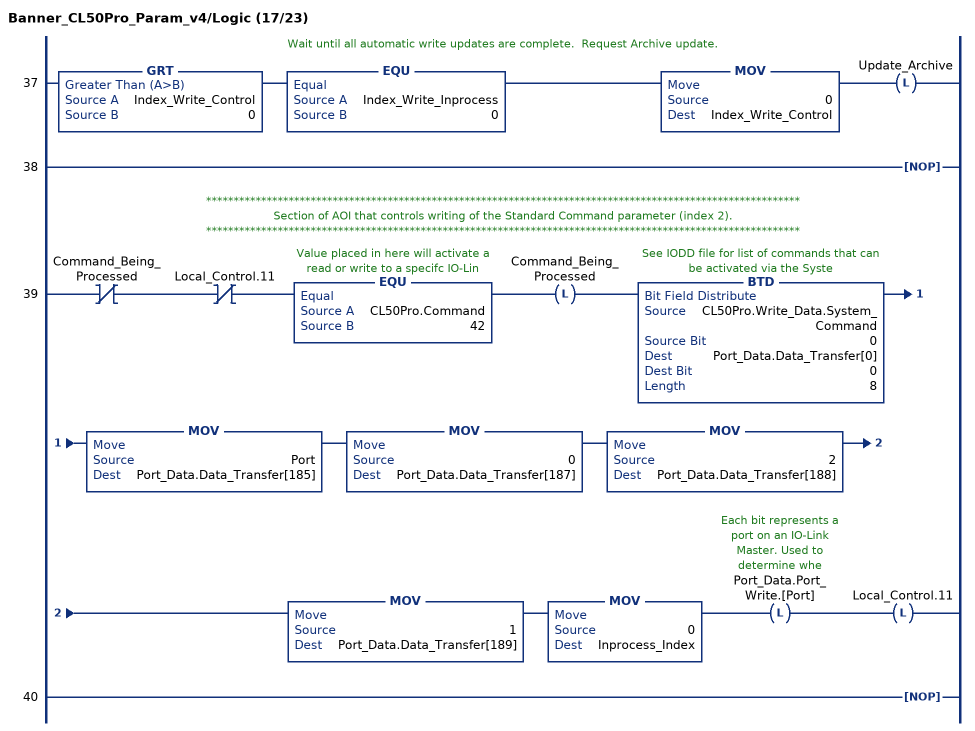
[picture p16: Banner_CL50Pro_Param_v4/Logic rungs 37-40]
   // Wait until all automatic write updates are complete.  Request Archive update.
   37: GRT(Index_Write_Control,0)EQU(Index_Write_Inprocess,0)MOV(0,Index_Write_Control)OTL(Update_Archive);
   38: NOP();
   // ************************************************************************************************************
   // Section of AOI that controls writing of the Standard Command parameter (index 2).
   // ************************************************************************************************************
   39: XIO(Command_Being_Processed)XIO(Local_Control.11)EQU(CL50Pro.Command,42)OTL(Command_Being_Processed)BTD(CL50Pro.Write_Data.System_Command,0,Port_Data.Data_Transfer[0],0,8)MOV(Port,Port_Data.Data_Transfer[185])MOV(0,Port_Data.Data_Transfer[187])MOV(2,Port_Data.Data_Transfer[188])MOV(1,Port_Data.Data_Transfer[189])MOV(0,Inprocess_Index)OTL(Port_Data.Port_Write.[Port])OTL(Local_Control.11);
   40: NOP();
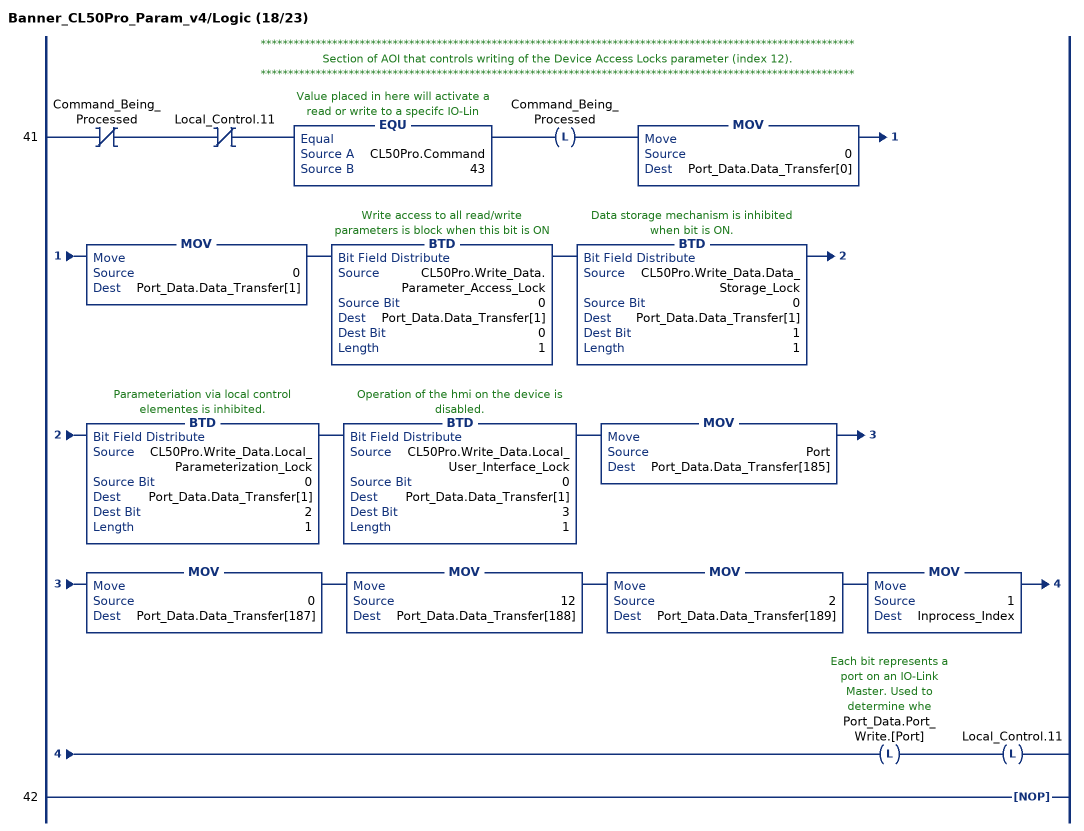
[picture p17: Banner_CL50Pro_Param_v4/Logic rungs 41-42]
   // ************************************************************************************************************
   // Section of AOI that controls writing of the Device Access Locks parameter (index 12).
   // ************************************************************************************************************
   41: XIO(Command_Being_Processed)XIO(Local_Control.11)EQU(CL50Pro.Command,43)OTL(Command_Being_Processed)MOV(0,Port_Data.Data_Transfer[0])MOV(0,Port_Data.Data_Transfer[1])BTD(CL50Pro.Write_Data.Parameter_Access_Lock,0,Port_Data.Data_Transfer[1],0,1)BTD(CL50Pro.Write_Data.Data_Storage_Lock,0,Port_Data.Data_Transfer[1],1,1)BTD(CL50Pro.Write_Data.Local_Parameterization_Lock,0,Port_Data.Data_Transfer[1],2,1)BTD(CL50Pro.Write_Data.Local_User_Interface_Lock,0,Port_Data.Data_Transfer[1],3,1)MOV(Port,Port_Data.Data_Transfer[185])MOV(0,Port_Data.Data_Transfer[187])MOV(12,Port_Data.Data_Transfer[188])MOV(2,Port_Data.Data_Transfer[189])MOV(1,Inprocess_Index)OTL(Port_Data.Port_Write.[Port])OTL(Local_Control.11);
   42: NOP();
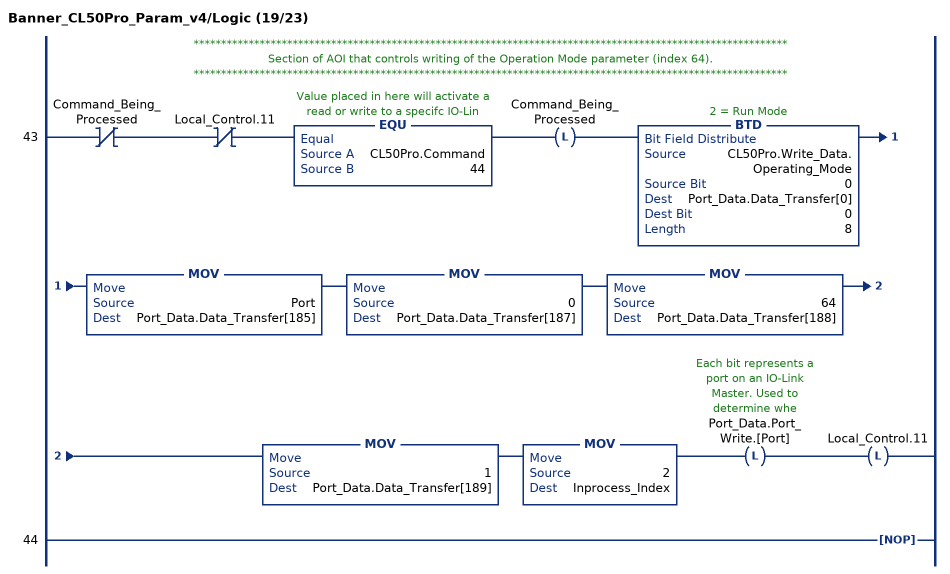
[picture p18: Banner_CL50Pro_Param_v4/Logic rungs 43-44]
   // ************************************************************************************************************
   // Section of AOI that controls writing of the Operation Mode parameter (index 64).
   // ************************************************************************************************************
   43: XIO(Command_Being_Processed)XIO(Local_Control.11)EQU(CL50Pro.Command,44)OTL(Command_Being_Processed)BTD(CL50Pro.Write_Data.Operating_Mode,0,Port_Data.Data_Transfer[0],0,8)MOV(Port,Port_Data.Data_Transfer[185])MOV(0,Port_Data.Data_Transfer[187])MOV(64,Port_Data.Data_Transfer[188])MOV(1,Port_Data.Data_Transfer[189])MOV(2,Inprocess_Index)OTL(Port_Data.Port_Write.[Port])OTL(Local_Control.11);
   44: NOP();
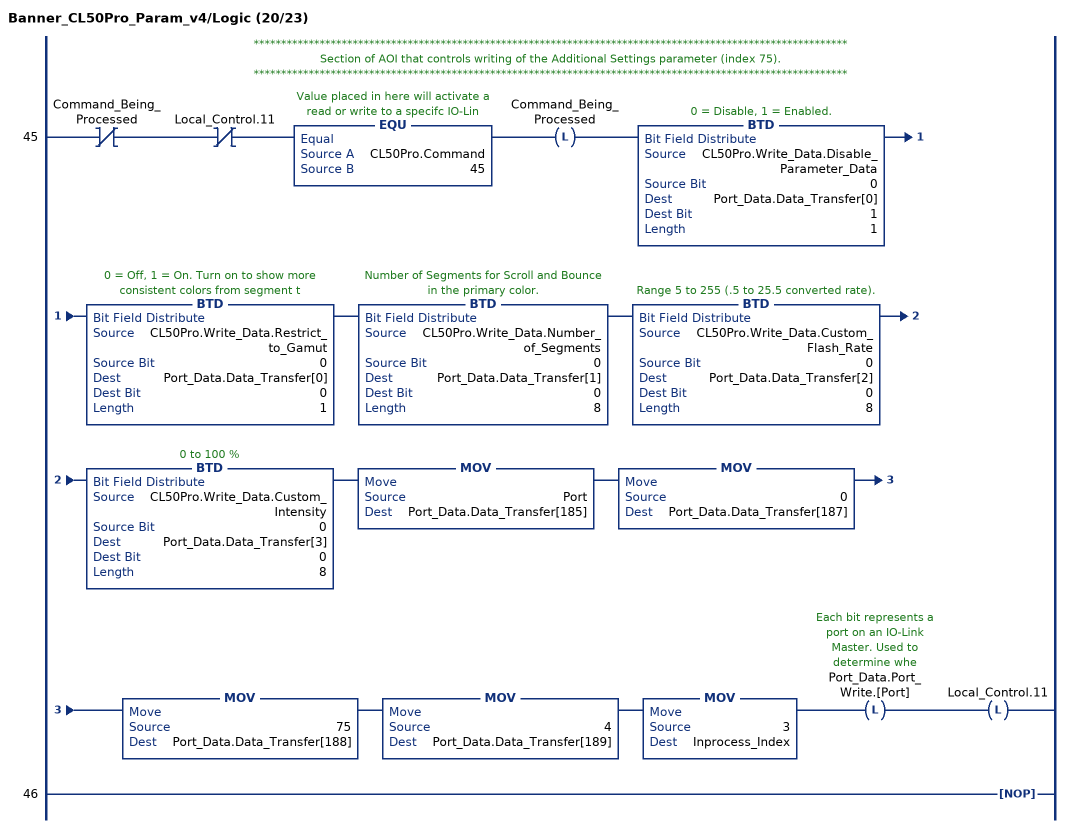
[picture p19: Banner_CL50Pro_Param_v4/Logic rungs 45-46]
   // ************************************************************************************************************
   // Section of AOI that controls writing of the Additional Settings parameter (index 75).
   // ************************************************************************************************************
   45: XIO(Command_Being_Processed)XIO(Local_Control.11)EQU(CL50Pro.Command,45)OTL(Command_Being_Processed)BTD(CL50Pro.Write_Data.Disable_Parameter_Data,0,Port_Data.Data_Transfer[0],1,1)BTD(CL50Pro.Write_Data.Restrict_to_Gamut,0,Port_Data.Data_Transfer[0],0,1)BTD(CL50Pro.Write_Data.Number_of_Segments,0,Port_Data.Data_Transfer[1],0,8)BTD(CL50Pro.Write_Data.Custom_Flash_Rate,0,Port_Data.Data_Transfer[2],0,8)BTD(CL50Pro.Write_Data.Custom_Intensity,0,Port_Data.Data_Transfer[3],0,8)MOV(Port,Port_Data.Data_Transfer[185])MOV(0,Port_Data.Data_Transfer[187])MOV(75,Port_Data.Data_Transfer[188])MOV(4,Port_Data.Data_Transfer[189])MOV(3,Inprocess_Index)OTL(Port_Data.Port_Write.[Port])OTL(Local_Control.11);
   46: NOP();
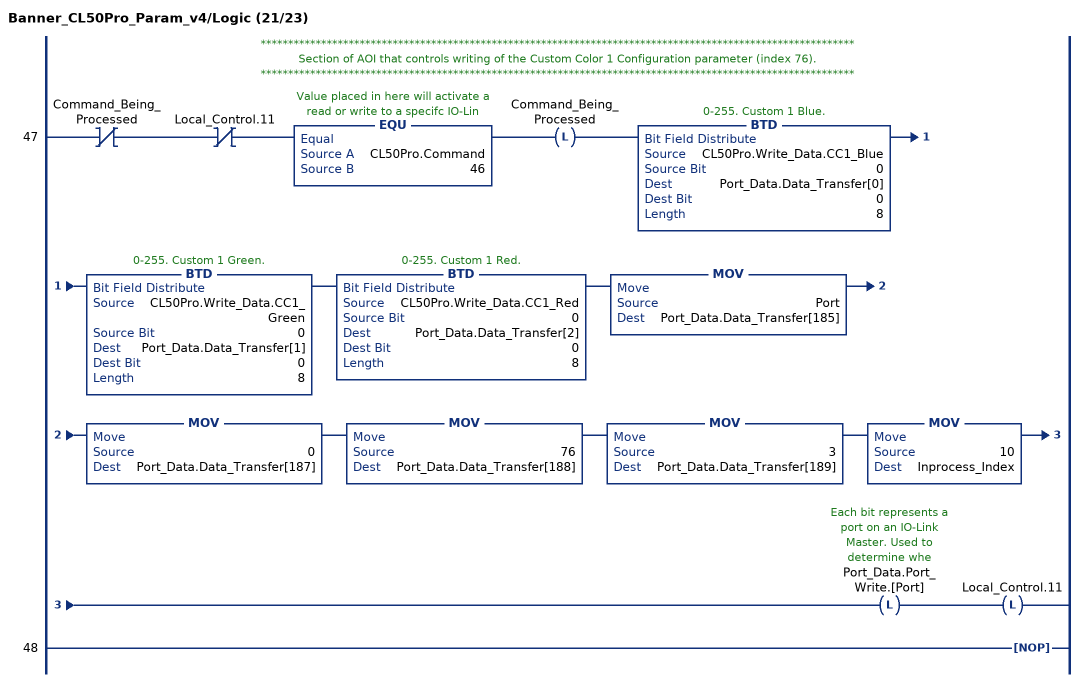
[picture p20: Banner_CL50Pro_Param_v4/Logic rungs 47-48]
   // ************************************************************************************************************
   // Section of AOI that controls writing of the Custom Color 1 Configuration parameter (index 76).
   // ************************************************************************************************************
   47: XIO(Command_Being_Processed)XIO(Local_Control.11)EQU(CL50Pro.Command,46)OTL(Command_Being_Processed)BTD(CL50Pro.Write_Data.CC1_Blue,0,Port_Data.Data_Transfer[0],0,8)BTD(CL50Pro.Write_Data.CC1_Green,0,Port_Data.Data_Transfer[1],0,8)BTD(CL50Pro.Write_Data.CC1_Red,0,Port_Data.Data_Transfer[2],0,8)MOV(Port,Port_Data.Data_Transfer[185])MOV(0,Port_Data.Data_Transfer[187])MOV(76,Port_Data.Data_Transfer[188])MOV(3,Port_Data.Data_Transfer[189])MOV(10,Inprocess_Index)OTL(Port_Data.Port_Write.[Port])OTL(Local_Control.11);
   48: NOP();
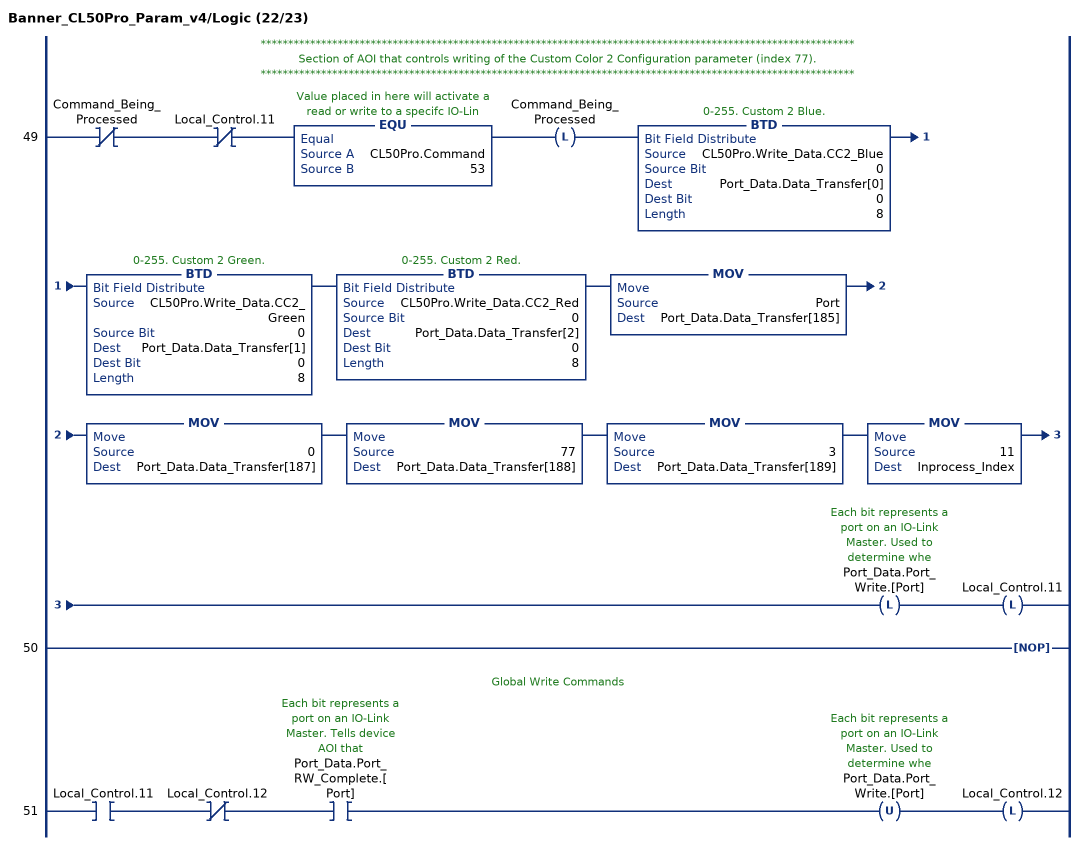
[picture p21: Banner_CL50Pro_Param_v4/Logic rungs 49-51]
   // ************************************************************************************************************
   // Section of AOI that controls writing of the Custom Color 2 Configuration parameter (index 77).
   // ************************************************************************************************************
   49: XIO(Command_Being_Processed)XIO(Local_Control.11)EQU(CL50Pro.Command,53)OTL(Command_Being_Processed)BTD(CL50Pro.Write_Data.CC2_Blue,0,Port_Data.Data_Transfer[0],0,8)BTD(CL50Pro.Write_Data.CC2_Green,0,Port_Data.Data_Transfer[1],0,8)BTD(CL50Pro.Write_Data.CC2_Red,0,Port_Data.Data_Transfer[2],0,8)MOV(Port,Port_Data.Data_Transfer[185])MOV(0,Port_Data.Data_Transfer[187])MOV(77,Port_Data.Data_Transfer[188])MOV(3,Port_Data.Data_Transfer[189])MOV(11,Inprocess_Index)OTL(Port_Data.Port_Write.[Port])OTL(Local_Control.11);
   50: NOP();
   // Global Write Commands
   51: XIC(Local_Control.11)XIO(Local_Control.12)XIC(Port_Data.Port_RW_Complete.[Port])OTU(Port_Data.Port_Write.[Port])OTL(Local_Control.12);
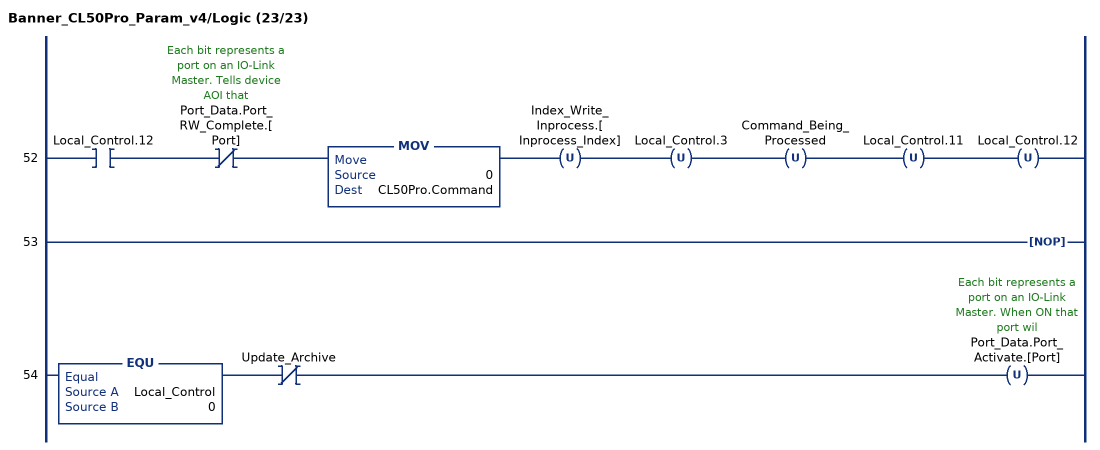
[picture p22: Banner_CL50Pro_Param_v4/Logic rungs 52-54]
   52: XIC(Local_Control.12)XIO(Port_Data.Port_RW_Complete.[Port])MOV(0,CL50Pro.Command)OTU(Index_Write_Inprocess.[Inprocess_Index])OTU(Local_Control.3)OTU(Command_Being_Processed)OTU(Local_Control.11)OTU(Local_Control.12);
   53: NOP();
   54: EQU(Local_Control,0)XIO(Update_Archive)OTU(Port_Data.Port_Activate.[Port]);
END_ROUTINE
END_ADD_ON_INSTRUCTION
